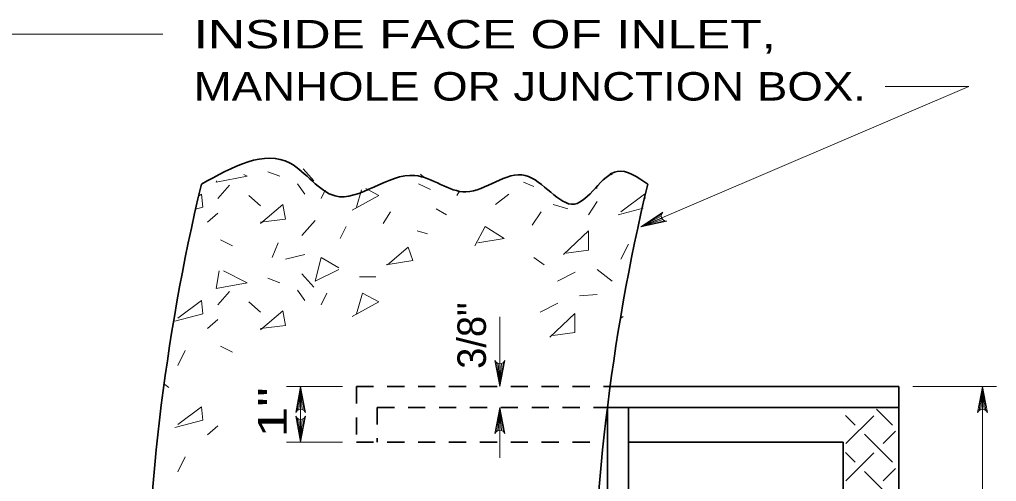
# Model space of a CAD drawing. Extents: x 16 to 133, y -56 to 112.
# Drawn here: x 62.26 to 97.27, y 95.61 to 112.17 of the extents above; entities that cross this region are included whole.
import ezdxf
from ezdxf.enums import TextEntityAlignment as Align

# ---------------------------------------------------------------- set-up
doc = ezdxf.new("R2010")
doc.units = 0
doc.header["$LTSCALE"] = 0.41
doc.linetypes.add('SHORT_DASHED', pattern=[2.7, 1.5, -1.2])
for name, color, linetype, lineweight in [('1', 7, 'Continuous', 35), ('10', 7, 'Continuous', 13), ('12', 7, 'Continuous', 53), ('13', 7, 'Continuous', 25), ('6', 7, 'Continuous', 13)]:
    doc.layers.add(name, color=color, linetype=linetype, lineweight=lineweight)

msp = doc.modelspace()

# ---------------------------------------------------------------- linework, layer by layer
at = {"layer": '1', "linetype": 'SHORT_DASHED'}
for p, q in [((74.3277, 99.017), (74.3277, 97.017)), ((74.3277, 99.017), (83.4245, 99.017)), ((75.0777, 98.267), (75.0777, 97.017)), ((75.0777, 98.267), (83.3277, 98.267)), ((74.3277, 97.017), (83.1839, 97.017))]:
    msp.add_line(p, q, dxfattribs=at)
at = {"layer": '1'}
for p, q in [((83.4245, 99.017), (93.7728, 99.017)), ((93.7728, 99.017), (93.7728, 79.517)), ((83.3277, 98.267), (83.3277, 80.267)), ((83.3277, 98.267), (93.7728, 98.267)), ((84.0777, 98.267), (84.0777, 80.267)), ((84.0777, 97.017), (91.7728, 97.017)), ((91.7728, 97.017), (91.7728, 81.517))]:
    msp.add_line(p, q, dxfattribs=at)
for centre in [(140.0228, 89.267), (156.0228, 89.267)]:
    msp.add_arc(centre, 73.25, 166.58032, 193.41967, dxfattribs=at)
msp.add_spline([(68.7728, 106.267), (71.9559, 107.0185), (73.5682, 105.8453), (76.4262, 106.5785), (78.2583, 105.9919), (80.3834, 106.5785), (82.1422, 105.552), (83.6811, 106.7252), (84.7728, 106.267)], degree=3, dxfattribs=at)
at = {"layer": '10'}
for p, q in [((67.387, 111.6433), (54.6853, 111.6433)), ((96.2808, 109.7733), (84.5282, 104.7337)), ((93.2837, 109.7733), (96.2808, 109.7733)), ((79.4717, 101.517), (79.4717, 99.017)), ((73.8277, 99.017), (71.8277, 99.017)), ((72.3277, 99.017), (72.3277, 97.017)), ((94.2728, 99.017), (97.2728, 99.017)), ((96.7728, 99.017), (96.7728, 79.517)), ((79.4717, 98.267), (79.4717, 96.4619)), ((73.8277, 97.017), (71.8277, 97.017))]:
    msp.add_line(p, q, dxfattribs=at)
for points in [[(84.5282, 104.7337), (85.316, 105.2616), (85.2696, 105.1876), (85.2601, 105.1156), (85.2749, 105.0539), (85.3094, 105.0007), (85.3681, 104.9578), (85.4537, 104.9404), (84.5282, 104.7337), (85.3681, 104.9578), (85.3094, 105.0007), (84.5282, 104.7337), (85.2749, 105.0539), (85.2601, 105.1156), (84.5282, 104.7337), (85.2696, 105.1876)], [(79.4717, 99.017), (79.2969, 99.949), (79.3467, 99.8772), (79.4092, 99.8402), (79.4717, 99.8295), (79.5342, 99.8402), (79.5967, 99.8772), (79.6465, 99.949), (79.4717, 99.017), (79.5967, 99.8772), (79.5342, 99.8402), (79.4717, 99.017), (79.4717, 99.8295), (79.4092, 99.8402), (79.4717, 99.017), (79.3467, 99.8772)], [(72.3277, 99.017), (72.5025, 98.0849), (72.4527, 98.1567), (72.3902, 98.1937), (72.3277, 98.2045), (72.2652, 98.1937), (72.2027, 98.1567), (72.153, 98.0849), (72.3277, 99.017), (72.2027, 98.1567), (72.2652, 98.1937), (72.3277, 99.017), (72.3277, 98.2045), (72.3902, 98.1937), (72.3277, 99.017), (72.4527, 98.1567)], [(96.7728, 99.017), (96.9475, 98.0849), (96.8978, 98.1567), (96.8353, 98.1937), (96.7728, 98.2045), (96.7103, 98.1937), (96.6478, 98.1567), (96.598, 98.0849), (96.7728, 99.017), (96.6478, 98.1567), (96.7103, 98.1937), (96.7728, 99.017), (96.7728, 98.2045), (96.8353, 98.1937), (96.7728, 99.017), (96.8978, 98.1567)], [(79.4717, 98.267), (79.6465, 97.3349), (79.5967, 97.4067), (79.5342, 97.4437), (79.4717, 97.4545), (79.4092, 97.4437), (79.3467, 97.4067), (79.2969, 97.3349), (79.4717, 98.267), (79.3467, 97.4067), (79.4092, 97.4437), (79.4717, 98.267), (79.4717, 97.4545), (79.5342, 97.4437), (79.4717, 98.267), (79.5967, 97.4067)], [(72.3277, 97.017), (72.153, 97.949), (72.2027, 97.8772), (72.2652, 97.8402), (72.3277, 97.8295), (72.3902, 97.8402), (72.4527, 97.8772), (72.5025, 97.949), (72.3277, 97.017), (72.4527, 97.8772), (72.3902, 97.8402), (72.3277, 97.017), (72.3277, 97.8295), (72.2652, 97.8402), (72.3277, 97.017), (72.2027, 97.8772)]]:
    msp.add_lwpolyline(points, dxfattribs=at)
at = {"layer": '6'}
for p, q in [((72.4245, 106.8121), (72.7991, 106.3906)), ((71.1576, 106.7083), (71.5812, 106.5494)), ((76.6221, 106.6263), (76.7705, 106.4965)), ((83.4265, 106.6575), (83.4953, 106.6024)), ((69.3573, 105.7551), (69.7809, 106.2317)), ((72.2167, 106.2847), (72.4814, 105.914)), ((76.5587, 106.2847), (76.9823, 106.0729)), ((80.3182, 106.3376), (80.6889, 106.1787)), ((82.8887, 106.1194), (82.9658, 106.1258)), ((70.4693, 105.861), (70.8929, 105.4904)), ((73.212, 106.0513), (73.0639, 105.7551)), ((74.5144, 106.0663), (74.3347, 105.4374)), ((77.9354, 105.861), (78.0248, 106.0175)), ((79.7887, 105.914), (79.3121, 105.5433)), ((81.3773, 105.5433), (81.9068, 105.3845)), ((82.6481, 105.1727), (82.9658, 105.6492)), ((83.7071, 105.1727), (84.6136, 105.4112)), ((68.9866, 104.9079), (69.3573, 105.2256)), ((75.2878, 104.855), (75.5526, 105.2786)), ((77.1941, 105.3845), (77.5648, 105.1727)), ((80.9536, 105.2786), (80.6359, 104.802)), ((72.8521, 104.9609), (72.3755, 104.4314)), ((73.9641, 104.7491), (73.7523, 104.3255)), ((76.5057, 104.5902), (76.8764, 104.4843)), ((69.4632, 104.2725), (69.8868, 104.0607)), ((71.5283, 104.1666), (71.3165, 103.6371)), ((83.813, 103.5841), (84.0778, 104.1136)), ((72.4814, 103.743), (71.7931, 103.5841)), ((80.6889, 103.6371), (81.0595, 103.3723)), ((72.3755, 103.0546), (72.7991, 102.5781)), ((82.1715, 103.1076), (81.5361, 102.7899)), ((82.9658, 103.2135), (83.4953, 102.7899)), ((71.1576, 102.8958), (71.5812, 102.7369)), ((74.4406, 102.9487), (75.0231, 102.9487)), ((69.3573, 101.9426), (69.7809, 102.4192)), ((72.2167, 102.4722), (72.4814, 102.1015)), ((73.2757, 102.3662), (73.0639, 101.9426)), ((82.3304, 102.2604), (82.9658, 102.3133)), ((70.4693, 102.0485), (70.8929, 101.6779)), ((81.5464, 101.9988), (80.911, 101.681)), ((68.9866, 101.0954), (69.3573, 101.4131)), ((83.8908, 101.5244), (83.813, 101.4661)), ((67.9276, 99.7716), (68.1924, 100.3011)), ((69.4632, 100.46), (69.8868, 100.2482)), ((67.4663, 99.0922), (67.6099, 98.9774)), ((93.5451, 97.6346), (92.9764, 98.2033)), ((91.8655, 97.9809), (92.2118, 97.6346)), ((91.8784, 96.9679), (92.8784, 97.9679)), ((68.9866, 97.2829), (69.3573, 97.6006)), ((93.653, 97.4092), (93.2118, 96.9679)), ((92.5451, 97.3013), (92.8784, 96.9679)), ((93.5451, 96.3013), (92.8784, 96.9679)), ((67.9276, 95.9591), (68.1924, 96.4886)), ((91.8655, 96.6476), (92.2118, 96.3013)), ((91.8784, 95.6346), (92.8784, 96.6346)), ((92.5451, 95.9679), (92.8784, 95.6346)), ((93.2118, 95.6346), (93.653, 96.0759)), ((93.5451, 94.9679), (92.8784, 95.6346))]:
    msp.add_line(p, q, dxfattribs=at)
for points in [[(69.3129, 106.3887), (69.3043, 106.3376), (70.4163, 106.5494), (70.2949, 106.6101)], [(74.1759, 105.3315), (75.129, 105.861), (74.6707, 106.111)], [(68.5648, 105.3682), (68.8278, 105.4374), (68.7748, 105.914), (68.6735, 105.838)], [(84.6778, 105.7563), (84.6602, 105.914), (83.813, 105.2786)], [(70.8929, 104.9079), (71.7931, 105.0138), (71.6872, 105.5433), (70.8929, 104.855)], [(78.5708, 104.0607), (78.9415, 104.7491), (79.6299, 104.3255), (78.6767, 104.1666)], [(81.8538, 103.7959), (82.6481, 103.9019), (82.6481, 104.5902), (81.7479, 103.743)], [(75.3937, 103.3723), (76.3469, 103.5312), (76.188, 104.0078), (75.4467, 103.3723)], [(73.6993, 103.2135), (72.8521, 102.7899), (73.0639, 103.6371), (73.6993, 103.2664)], [(69.4102, 103.1605), (69.3043, 102.5251), (70.4163, 102.7369), (69.5691, 103.1605)], [(74.1759, 101.519), (75.129, 102.0485), (74.5465, 102.3662), (74.3347, 101.6249)], [(67.8217, 101.3602), (68.8278, 101.6249), (68.7748, 102.1015), (67.9276, 101.4661)], [(70.8929, 101.0954), (71.7931, 101.2013), (71.6872, 101.7308), (70.8929, 101.0425)], [(81.3708, 100.839), (82.165, 100.945), (82.165, 101.6333), (81.2649, 100.7861)], [(67.8217, 97.5477), (68.8278, 97.8124), (68.7748, 98.289), (67.9276, 97.6536)]]:
    msp.add_lwpolyline(points, dxfattribs=at)

# ---------------------------------------------------------------- texts
at = {"layer": '12'}
for s, width, p in [('INSIDE FACE OF INLET,', 1.35, (68.4969, 111.1333)), ('MANHOLE OR JUNCTION BOX.', 1.2, (68.4969, 109.2633))]:
    msp.add_text(s, height=1.02, dxfattribs=dict(at, width=width)).set_placement(p)
at = {"layer": '13'}
msp.add_text('3/8"', height=1.02, rotation=90, dxfattribs=at).set_placement((78.9717, 100.8386), align=Align.CENTER)
at = {"layer": '13', "width": 1.45}
msp.add_text('1"', height=1.02, rotation=90, dxfattribs=at).set_placement((71.8277, 98.0886), align=Align.CENTER)

doc.saveas('drawing.dxf')
